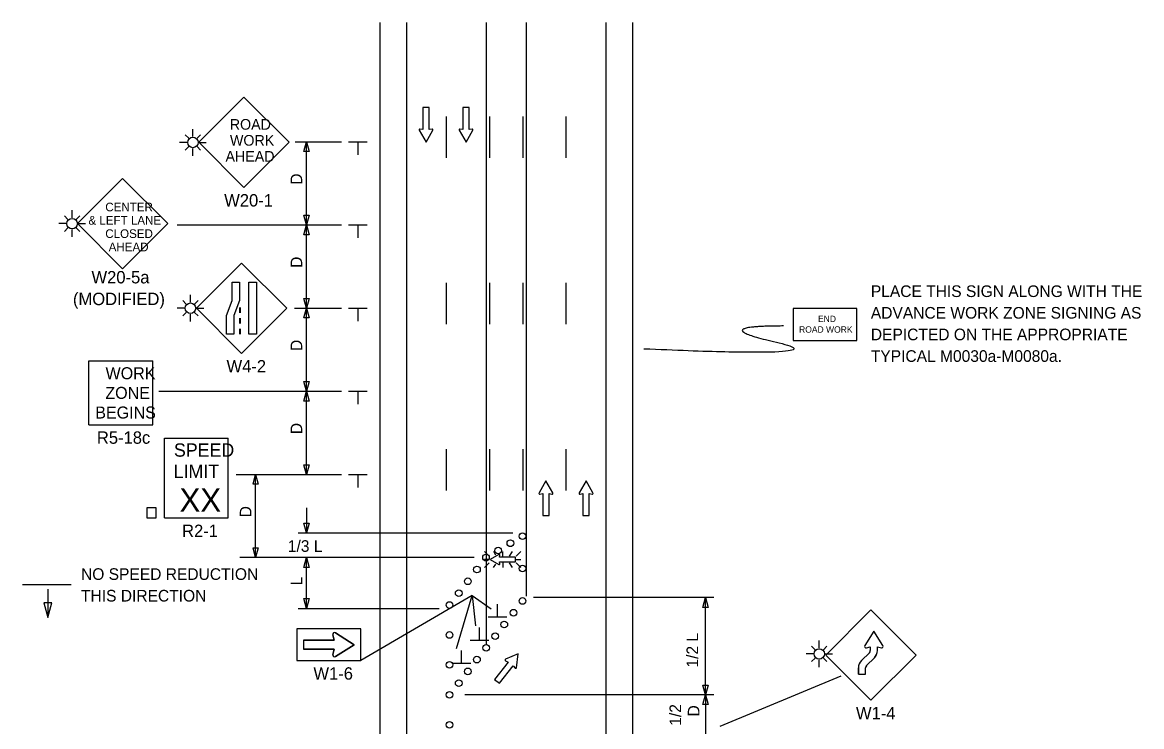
# Model space of a CAD drawing. Extents: x 16730 to 19504, y 5697 to 6911.
# Drawn here: x 16732 to 17406, y 6488 to 6911 of the extents above; entities that cross this region are included whole.
import ezdxf

# ---------------------------------------------------------------- set-up
doc = ezdxf.new("R2010")
doc.units = 0
for name, color, linetype in [('ALI_LEGAL_EX', 7, 'Continuous'), ('MT_SCRATCH_LEVEL_E', 7, 'Continuous'), ('PAVT_EDGE_EX', 7, 'Continuous'), ('TRAFFIC_SIGNS_PR', 7, 'Continuous'), ('TYPICAL_TEXT_DIMEN_PR', 7, 'Continuous')]:
    doc.layers.add(name, color=color, linetype=linetype)

msp = doc.modelspace()

# ---------------------------------------------------------------- linework, layer by layer
at = {"layer": 'ALI_LEGAL_EX'}
for points in [[(16987.43, 6854.77), (16987.43, 6829.77)], [(17013.43, 6854.77), (17013.43, 6829.77)], [(17033.43, 6854.77), (17033.43, 6829.77)], [(17059.43, 6854.77), (17059.43, 6829.77)], [(16987.43, 6754.77), (16987.43, 6729.77)], [(17013.43, 6754.77), (17013.43, 6729.77)], [(17033.43, 6754.77), (17033.43, 6729.77)], [(17059.43, 6754.77), (17059.43, 6729.77)], [(16987.43, 6654.77), (16987.43, 6629.77)], [(17013.43, 6654.77), (17013.43, 6629.77)], [(17033.43, 6654.77), (17033.43, 6629.77)], [(17059.43, 6654.77), (17059.43, 6629.77)]]:
    msp.add_lwpolyline(points, dxfattribs=at)
at = {"layer": 'MT_SCRATCH_LEVEL_E'}
for p, q in [((16977.1, 6860.07), (16973.36, 6860.07)), ((16973.36, 6860.07), (16973.36, 6846.81)), ((16977.1, 6860.07), (16973.36, 6860.07)), ((16973.36, 6860.07), (16973.36, 6846.81)), ((16977.1, 6846.81), (16977.1, 6860.07)), ((16977.1, 6846.81), (16977.1, 6860.07)), ((17001.17, 6860.07), (16997.43, 6860.07)), ((16997.43, 6860.07), (16997.43, 6846.81)), ((17001.17, 6860.07), (16997.43, 6860.07)), ((16997.43, 6860.07), (16997.43, 6846.81)), ((17001.17, 6846.81), (17001.17, 6860.07)), ((17001.17, 6846.81), (17001.17, 6860.07)), ((16971.1, 6846.44), (16975.25, 6839.2)), ((16971.1, 6846.44), (16975.25, 6839.2)), ((16973.36, 6846.81), (16971.58, 6847.12)), ((16973.36, 6846.81), (16971.58, 6847.12)), ((16975.25, 6839.2), (16979.36, 6846.44)), ((16975.25, 6839.2), (16979.36, 6846.44)), ((16978.88, 6847.12), (16977.1, 6846.81)), ((16978.88, 6847.12), (16977.1, 6846.81)), ((16995.18, 6846.44), (16999.32, 6839.2)), ((16995.18, 6846.44), (16999.32, 6839.2)), ((16997.43, 6846.81), (16995.65, 6847.12)), ((16997.43, 6846.81), (16995.65, 6847.12)), ((16999.32, 6839.2), (17003.43, 6846.44)), ((16999.32, 6839.2), (17003.43, 6846.44)), ((17002.95, 6847.12), (17001.17, 6846.81)), ((17002.95, 6847.12), (17001.17, 6846.81)), ((17047.37, 6635.6), (17043.26, 6628.36)), ((17047.37, 6635.6), (17043.26, 6628.36)), ((17051.52, 6628.36), (17047.37, 6635.6)), ((17051.52, 6628.36), (17047.37, 6635.6)), ((17071.54, 6635.6), (17067.43, 6628.36)), ((17071.54, 6635.6), (17067.43, 6628.36)), ((17075.69, 6628.36), (17071.54, 6635.6)), ((17075.69, 6628.36), (17071.54, 6635.6)), ((17043.74, 6627.67), (17045.52, 6627.99)), ((17043.74, 6627.67), (17045.52, 6627.99)), ((17045.52, 6627.99), (17045.52, 6614.73)), ((17045.52, 6627.99), (17045.52, 6614.73)), ((17049.26, 6614.73), (17049.26, 6627.99)), ((17049.26, 6627.99), (17051.04, 6627.67)), ((17049.26, 6614.73), (17049.26, 6627.99)), ((17049.26, 6627.99), (17051.04, 6627.67)), ((17067.91, 6627.67), (17069.69, 6627.99)), ((17067.91, 6627.67), (17069.69, 6627.99)), ((17069.69, 6627.99), (17069.69, 6614.73)), ((17069.69, 6627.99), (17069.69, 6614.73)), ((17073.43, 6614.73), (17073.43, 6627.99)), ((17073.43, 6627.99), (17075.21, 6627.67)), ((17073.43, 6614.73), (17073.43, 6627.99)), ((17073.43, 6627.99), (17075.21, 6627.67)), ((17045.52, 6614.73), (17049.26, 6614.73)), ((17045.52, 6614.73), (17049.26, 6614.73)), ((17069.69, 6614.73), (17073.43, 6614.73)), ((17069.69, 6614.73), (17073.43, 6614.73)), ((17024.64, 6526.66), (17016.51, 6516.2)), ((17024.64, 6526.66), (17016.51, 6516.2)), ((17023.05, 6527.5), (17024.64, 6526.66)), ((17023.05, 6527.5), (17024.64, 6526.66)), ((17030.78, 6531.53), (17023.09, 6528.34)), ((17030.78, 6531.53), (17023.09, 6528.34)), ((17029.61, 6523.27), (17030.78, 6531.53)), ((17029.61, 6523.27), (17030.78, 6531.53)), ((17019.46, 6513.9), (17027.6, 6524.36)), ((17019.46, 6513.9), (17027.6, 6524.36)), ((17027.6, 6524.36), (17028.81, 6523.03)), ((17027.6, 6524.36), (17028.81, 6523.03)), ((17016.51, 6516.2), (17019.46, 6513.9)), ((17016.51, 6516.2), (17019.46, 6513.9))]:
    msp.add_line(p, q, dxfattribs=at)
for centre, start, end in [((16971.51, 6846.66), 80.03619, 209.77312), ((16971.51, 6846.66), 80.03619, 209.77312), ((16978.96, 6846.67), 330.42484, 99.96381), ((16978.96, 6846.67), 330.42484, 99.96381), ((16995.59, 6846.66), 80.03619, 209.77312), ((16995.59, 6846.66), 80.03619, 209.77312), ((17003.03, 6846.67), 330.42484, 99.96381), ((17003.03, 6846.67), 330.42484, 99.96381), ((17043.67, 6628.13), 150.42484, 279.96381), ((17043.67, 6628.13), 150.42484, 279.96381), ((17051.11, 6628.13), 260.03619, 29.77312), ((17051.11, 6628.13), 260.03619, 29.77312), ((17067.84, 6628.13), 150.42484, 279.96381), ((17067.84, 6628.13), 150.42484, 279.96381), ((17075.28, 6628.13), 260.03619, 29.77312), ((17075.28, 6628.13), 260.03619, 29.77312), ((17023.27, 6527.91), 112.55885, 242.09782), ((17023.27, 6527.91), 112.55885, 242.09782), ((17029.15, 6523.35), 222.17021, 351.90713), ((17029.15, 6523.35), 222.17021, 351.90713)]:
    msp.add_arc(centre, 0.463, start, end, dxfattribs=at)
at = {"layer": 'PAVT_EDGE_EX'}
for p, q in [((16947.43, 6911.29), (16947.43, 6081.05)), ((16963.43, 6911.29), (16963.43, 6081.05)), ((17011.43, 6911.29), (17011.43, 6536.81)), ((17035.43, 6911.29), (17035.43, 6566.36)), ((17083.43, 6911.29), (17083.43, 6081.05)), ((17099.43, 6911.29), (17099.43, 6081.05))]:
    msp.add_line(p, q, dxfattribs=at)
at = {"layer": 'TRAFFIC_SIGNS_PR'}
for p, q in [((16865.66, 6866.41), (16838.48, 6839.22)), ((16892.85, 6839.22), (16865.66, 6866.41)), ((16832.5, 6841.63), (16830.4, 6843.73)), ((16835.02, 6842.67), (16835.02, 6847.17)), ((16837.53, 6841.63), (16839.64, 6843.73)), ((16831.86, 6839.11), (16827.02, 6839.11)), ((16832.5, 6836.6), (16830.4, 6834.49)), ((16835.02, 6831.15), (16835.02, 6835.56)), ((16837.53, 6836.6), (16839.64, 6834.49)), ((16838.17, 6839.11), (16843.05, 6839.11)), ((16838.48, 6839.22), (16865.66, 6812.04)), ((16865.66, 6812.04), (16892.85, 6839.22)), ((16792.68, 6817.45), (16765.49, 6790.27)), ((16819.87, 6790.27), (16792.68, 6817.45)), ((16759.83, 6792.78), (16757.72, 6794.89)), ((16762.34, 6793.82), (16762.34, 6798.32)), ((16764.85, 6792.78), (16766.96, 6794.89)), ((16759.18, 6790.27), (16754.35, 6790.27)), ((16759.82, 6787.76), (16757.72, 6785.65)), ((16764.85, 6787.76), (16766.96, 6785.65)), ((16765.49, 6790.27), (16770.37, 6790.27)), ((16765.49, 6790.27), (16792.68, 6763.08)), ((16792.68, 6763.08), (16819.87, 6790.27)), ((16762.34, 6782.3), (16762.34, 6786.71)), ((16864.28, 6766.57), (16837.13, 6739.42)), ((16891.44, 6739.42), (16864.28, 6766.57)), ((16833.52, 6742.97), (16833.52, 6747.47)), ((16831, 6741.93), (16828.9, 6744.04)), ((16836.03, 6741.93), (16838.14, 6744.04)), ((16830.36, 6739.42), (16825.52, 6739.42)), ((16831, 6736.9), (16828.9, 6734.79)), ((16833.52, 6731.45), (16833.52, 6735.86)), ((16836.03, 6736.9), (16838.14, 6734.8)), ((16836.67, 6739.42), (16841.55, 6739.42)), ((16837.13, 6739.42), (16864.28, 6712.26)), ((16863.04, 6739.91), (16863.04, 6736.71)), ((16863.44, 6739.91), (16863.44, 6736.71)), ((16864.28, 6712.26), (16891.44, 6739.42)), ((16863.04, 6733.51), (16863.04, 6730.31)), ((16863.04, 6727.11), (16863.04, 6723.91)), ((16863.44, 6733.51), (16863.44, 6730.31)), ((16863.44, 6727.11), (16863.44, 6723.91)), ((16772.45, 6669.36), (16772.45, 6707.76)), ((16772.45, 6707.76), (16810.85, 6707.76)), ((16810.85, 6669.36), (16810.85, 6707.76)), ((16772.45, 6669.36), (16810.85, 6669.36)), ((16817.83, 6661.29), (16856.23, 6661.29)), ((16817.83, 6613.29), (16817.83, 6661.29)), ((16856.23, 6613.29), (16856.23, 6661.29)), ((16817.83, 6613.29), (16856.23, 6613.29)), ((17010.52, 6593.2), (17013.34, 6590.39)), ((17017.24, 6591.02), (17015.98, 6593.2)), ((17021.42, 6590.39), (17021.42, 6593.2)), ((17025.56, 6590.39), (17027.19, 6593.2)), ((17029.51, 6590.39), (17032.33, 6593.21)), ((17013.34, 6588.35), (17010.52, 6588.35)), ((17010.52, 6583.5), (17013.34, 6586.32)), ((17021.42, 6586.32), (17021.42, 6583.5)), ((17027.21, 6583.5), (17025.58, 6586.32)), ((17029.51, 6588.35), (17032.33, 6588.35)), ((17029.51, 6586.32), (17032.33, 6583.5)), ((17015.95, 6583.5), (17017.16, 6585.59)), ((17242.92, 6557.97), (17215.77, 6530.82)), ((17270.07, 6530.82), (17242.92, 6557.97)), ((16901.58, 6539.92), (16919.98, 6539.92)), ((16901.58, 6539.92), (16901.58, 6534.32)), ((16919.98, 6539.92), (16919.14, 6542.98)), ((16920.82, 6544.22), (16931.98, 6537.12)), ((17211.86, 6535.09), (17211.86, 6539.59)), ((16919.98, 6534.32), (16901.58, 6534.32)), ((16919.14, 6531.26), (16919.98, 6534.32)), ((16931.98, 6537.12), (16920.82, 6530.02)), ((17209.34, 6534.05), (17207.24, 6536.16)), ((17214.37, 6534.05), (17216.48, 6536.16)), ((17237.26, 6527.57), (17241.98, 6532.28)), ((17241.98, 6532.28), (17237.26, 6527.57)), ((17208.7, 6531.54), (17203.87, 6531.54)), ((17209.34, 6529.03), (17207.24, 6526.92)), ((17211.86, 6523.57), (17211.86, 6527.98)), ((17214.37, 6529.03), (17216.48, 6526.92)), ((17215.01, 6531.54), (17219.89, 6531.54)), ((17215.77, 6530.82), (17242.92, 6503.67)), ((17240.32, 6524.52), (17245.03, 6529.23)), ((17240.32, 6524.52), (17245.03, 6529.23)), ((17242.92, 6503.67), (17270.07, 6530.82)), ((17235.4, 6519.45), (17235.4, 6523.15)), ((17235.4, 6519.45), (17239.71, 6519.45)), ((17239.71, 6519.45), (17239.71, 6523.15))]:
    msp.add_line(p, q, dxfattribs=at)
for points in [[(16863.04, 6755.15), (16863.04, 6743.97), (16859.69, 6735.09), (16859.69, 6723.91), (16855.2, 6723.91), (16855.2, 6735.09), (16858.54, 6743.97), (16858.54, 6755.15)], [(16873.17, 6755.15), (16873.17, 6723.91), (16868.68, 6723.91), (16868.68, 6755.15)], [(17196.1, 6719.96), (17234.5, 6719.96), (17234.5, 6739.16), (17196.1, 6739.16)], [(16807.23, 6613.29), (16812.82, 6613.29), (16812.82, 6619.46), (16807.23, 6619.46)], [(16897.58, 6527.52), (16935.98, 6527.52), (16935.98, 6546.72), (16897.58, 6546.72)]]:
    msp.add_lwpolyline(points, close=True, dxfattribs=at)
for points in [[(17019.1, 6591.37), (17013.79, 6588.35), (17019.1, 6585.31)], [(17019.6, 6585.67), (17019.37, 6586.97), (17029.09, 6586.97), (17029.09, 6589.71), (17019.37, 6589.71), (17019.6, 6591.01)], [(16919.14, 6542.98), (16919.98, 6539.92), (16901.58, 6539.92), (16901.58, 6534.32), (16919.98, 6534.32), (16919.14, 6531.26)], [(16920.82, 6530.02), (16931.98, 6537.12), (16920.82, 6544.22)], [(17250.19, 6536.56), (17244.7, 6545.17), (17239.22, 6536.56)], [(17250.18, 6536.56), (17244.7, 6545.17), (17239.22, 6536.56)], [(17240.18, 6535.26), (17242.54, 6535.91), (17242.54, 6533.61)], [(17240.18, 6535.26), (17241.02, 6535.49), (17242.54, 6535.91), (17242.54, 6533.61)], [(17246.85, 6533.54), (17246.86, 6535.91), (17249.22, 6535.26)], [(17235.4, 6523.15), (17235.4, 6519.45), (17239.71, 6519.45), (17239.71, 6523.15)]]:
    msp.add_lwpolyline(points, dxfattribs=at)
for centre, radius in [((16835.02, 6839.11), 3.15), ((16762.34, 6790.27), 3.15), ((16833.52, 6739.42), 3.15), ((17025.99, 6598.09), 2), ((17033.32, 6602.39), 2), ((17018.66, 6593.78), 2), ((17011.34, 6589.47), 2), ((17005.92, 6582.34), 2), ((17033.32, 6582.9), 2), ((17000.42, 6575.21), 2), ((16994.93, 6568.08), 2), ((16989.44, 6560.95), 2), ((16989.44, 6560.95), 2), ((17033.32, 6563.4), 2), ((17027.84, 6556.34), 2), ((17022.35, 6549.29), 2), ((16989.44, 6542.95), 2), ((17016.87, 6542.23), 2), ((17011.38, 6535.18), 2), ((17211.86, 6531.54), 3.15), ((16989.44, 6524.95), 2), ((17005.89, 6528.12), 2), ((17000.41, 6521.06), 2), ((16994.92, 6514.01), 2), ((16989.43, 6506.95), 2), ((16989.44, 6488.95), 2)]:
    msp.add_circle(centre, radius, dxfattribs=at)
for centre, radius, start, end in [((17019.26, 6591.07), 0.341, 350.73078, 118.89165), ((17019.26, 6585.61), 0.341, 241.48329, 9.95933), ((16920.22, 6543.28), 1.12, 57.53038, 195.32692), ((16920.22, 6543.28), 1.12, 57.53038, 195.32692), ((17239.95, 6536.09), 0.864, 147.52044, 285.3986), ((17239.95, 6536.09), 0.866, 147.52881, 285.38519), ((17240.69, 6533.61), 1.85, 314.21254, 0), ((17240.69, 6533.61), 1.85, 314.2123, 0.1238), ((17240.69, 6533.61), 6.17, 314.21254, 359.38189), ((17240.69, 6533.61), 6.17, 314.76872, 359.37555), ((17249.45, 6536.1), 0.866, 254.67989, 32.28036), ((16920.22, 6530.96), 1.12, 164.67308, 302.46962), ((16920.22, 6530.96), 1.12, 164.67308, 302.46963), ((17241.56, 6523.15), 6.17, 134.21254, 180), ((17241.56, 6523.15), 6.17, 134.21254, 180), ((17241.57, 6523.15), 6.17, 134.21172, 180), ((17241.56, 6523.15), 1.85, 134.21254, 180), ((17241.57, 6523.15), 1.85, 132.37199, 180)]:
    msp.add_arc(centre, radius, start, end, dxfattribs=at)
msp.add_open_spline([(17190.41, 6728.74), (17143.17, 6728.74), (17228.2, 6709.4), (17106.38, 6714.89)], degree=2, dxfattribs=at)
at = {"layer": 'TYPICAL_TEXT_DIMEN_PR'}
for p, q in [((16896.48, 6839.48), (16924.34, 6839.48)), ((16898.34, 6839.48), (16924.34, 6839.48)), ((16901.77, 6833.61), (16903.34, 6839.48)), ((16903.34, 6789.48), (16903.34, 6839.48)), ((16903.34, 6839.48), (16904.91, 6833.61)), ((16928.59, 6839.48), (16939.84, 6839.48)), ((16934.21, 6839.48), (16934.21, 6831.69)), ((16903.34, 6833.61), (16901.77, 6833.61)), ((16904.91, 6833.61), (16903.34, 6833.61)), ((16903.34, 6789.48), (16901.77, 6795.34)), ((16901.77, 6795.34), (16903.34, 6795.34)), ((16903.34, 6795.34), (16904.91, 6795.34)), ((16904.91, 6795.34), (16903.34, 6789.48)), ((16825.58, 6789.48), (16924.34, 6789.48)), ((16898.34, 6789.48), (16924.34, 6789.48)), ((16901.77, 6783.61), (16903.34, 6789.48)), ((16903.34, 6789.48), (16904.91, 6783.61)), ((16903.34, 6739.48), (16903.34, 6789.48)), ((16928.59, 6789.48), (16939.84, 6789.48)), ((16934.21, 6789.48), (16934.21, 6781.69)), ((16903.34, 6783.61), (16901.77, 6783.61)), ((16904.91, 6783.61), (16903.34, 6783.61)), ((16903.34, 6739.48), (16901.77, 6745.34)), ((16901.77, 6745.34), (16903.34, 6745.34)), ((16903.34, 6745.34), (16904.91, 6745.34)), ((16904.91, 6745.34), (16903.34, 6739.48)), ((16896.04, 6739.48), (16924.34, 6739.48)), ((16901.77, 6733.61), (16903.34, 6739.48)), ((16903.34, 6739.48), (16904.91, 6733.61)), ((16903.34, 6689.48), (16903.34, 6739.48)), ((16928.59, 6739.48), (16939.84, 6739.48)), ((16934.21, 6739.48), (16934.21, 6731.69)), ((16903.34, 6733.61), (16901.77, 6733.61)), ((16904.91, 6733.61), (16903.34, 6733.61)), ((16903.34, 6689.48), (16901.77, 6695.34)), ((16901.77, 6695.34), (16903.34, 6695.34)), ((16903.34, 6695.34), (16904.91, 6695.34)), ((16904.91, 6695.34), (16903.34, 6689.48)), ((16814.42, 6689.48), (16924.34, 6689.48)), ((16901.77, 6683.61), (16903.34, 6689.48)), ((16903.34, 6639.48), (16903.34, 6689.48)), ((16903.34, 6689.48), (16904.91, 6683.61)), ((16928.59, 6689.48), (16939.84, 6689.48)), ((16934.21, 6689.48), (16934.21, 6681.69)), ((16903.34, 6683.61), (16901.77, 6683.61)), ((16904.91, 6683.61), (16903.34, 6683.61)), ((16903.34, 6639.48), (16901.77, 6645.34)), ((16901.77, 6645.34), (16903.34, 6645.34)), ((16903.34, 6645.34), (16904.91, 6645.34)), ((16904.91, 6645.34), (16903.34, 6639.48)), ((16861.13, 6639.48), (16924.34, 6639.48)), ((16871.19, 6633.61), (16872.76, 6639.48)), ((16872.76, 6633.61), (16871.19, 6633.61)), ((16872.76, 6639.48), (16874.33, 6633.61)), ((16872.76, 6589.48), (16872.76, 6639.48)), ((16874.33, 6633.61), (16872.76, 6633.61)), ((16928.59, 6639.48), (16939.84, 6639.48)), ((16934.21, 6639.48), (16934.21, 6631.69)), ((16903.34, 6619.32), (16903.34, 6604.4)), ((16903.34, 6604.4), (16901.77, 6610.26)), ((16901.77, 6610.26), (16903.34, 6610.26)), ((16903.34, 6610.26), (16904.91, 6610.26)), ((16904.91, 6610.26), (16903.34, 6604.4)), ((16898.34, 6604.4), (17027.47, 6604.4)), ((16872.76, 6589.48), (16871.19, 6595.34)), ((16871.19, 6595.34), (16872.76, 6595.34)), ((16872.76, 6595.34), (16874.33, 6595.34)), ((16874.33, 6595.34), (16872.76, 6589.48)), ((17004.25, 6589.48), (16863.24, 6589.48)), ((17004.25, 6589.48), (16872.76, 6589.48)), ((16901.77, 6583.61), (16903.34, 6589.48)), ((16903.34, 6558.94), (16903.34, 6589.48)), ((16903.34, 6589.48), (16904.91, 6583.61)), ((16903.34, 6583.61), (16901.77, 6583.61)), ((16904.91, 6583.61), (16903.34, 6583.61)), ((16761.85, 6573.04), (16732.41, 6573.04)), ((16747.67, 6570.54), (16747.67, 6553.42)), ((17003.11, 6566.74), (16935.98, 6527.52)), ((16993.63, 6534.8), (17003.11, 6566.74)), ((17003.11, 6566.74), (17005.01, 6548.49)), ((17003.11, 6566.74), (17014.49, 6558.76)), ((16747.67, 6562.21), (16745.32, 6562.21)), ((16745.32, 6562.21), (16747.67, 6553.42)), ((16747.67, 6553.42), (16750.03, 6562.21)), ((16750.03, 6562.21), (16747.67, 6562.21)), ((16898.34, 6558.94), (16983.16, 6558.94)), ((16903.34, 6558.94), (16901.77, 6564.8)), ((16901.77, 6564.8), (16903.34, 6564.8)), ((16903.34, 6564.8), (16904.91, 6564.8)), ((16904.91, 6564.8), (16903.34, 6558.94)), ((17018.34, 6553.59), (17018.34, 6561.38)), ((17148.43, 6565.4), (17039.85, 6565.4)), ((17141.86, 6559.54), (17143.43, 6565.4)), ((17143.43, 6559.54), (17141.86, 6559.54)), ((17143.43, 6506.95), (17143.43, 6565.4)), ((17143.43, 6565.4), (17145, 6559.54)), ((17145, 6559.54), (17143.43, 6559.54)), ((17023.97, 6553.59), (17012.72, 6553.59)), ((17007.51, 6539.66), (17007.51, 6547.45)), ((17013.14, 6539.66), (17001.89, 6539.66)), ((16996.69, 6525.74), (16996.69, 6533.52)), ((17002.31, 6525.74), (16991.06, 6525.74)), ((17143.43, 6506.95), (17141.86, 6512.81)), ((17141.86, 6512.81), (17143.43, 6512.81)), ((17143.43, 6512.81), (17145, 6512.81)), ((17145, 6512.81), (17143.43, 6506.95)), ((17224.76, 6518.18), (17151.94, 6487.89)), ((17148.43, 6506.95), (16998.6, 6506.95)), ((17141.86, 6501.09), (17143.43, 6506.95)), ((17143.43, 6506.95), (17145, 6501.09)), ((17143.43, 6506.95), (17143.43, 6481.95)), ((17143.43, 6501.09), (17141.86, 6501.09)), ((17145, 6501.09), (17143.43, 6501.09))]:
    msp.add_line(p, q, dxfattribs=at)

# ---------------------------------------------------------------- texts
at = {"layer": 'TRAFFIC_SIGNS_PR'}
for s, height, p in [('ROAD', 6.408, (16857.19, 6846.77)), ('WORK', 6.408, (16857.3, 6837.16)), ('AHEAD', 6.408, (16854.61, 6827.54)), ('W20-1', 7.449, (16853.82, 6800.58)), ('CENTER', 5.206, (16782.3, 6797.68)), ('& LEFT LANE', 5.2065, (16772.16, 6789.67)), ('CLOSED', 5.206, (16782.3, 6781.66)), ('AHEAD', 5.206, (16784.33, 6773.65)), ('W20-5a', 7.449, (16773.99, 6754.35)), ('(MODIFIED)', 7.449, (16762.83, 6741.3)), ('PLACE THIS SIGN ALONG WITH THE', 7, (17242.88, 6746.16)), ('END', 3.831, (17211.1, 6731.09)), ('ADVANCE WORK ZONE SIGNING AS', 7, (17242.88, 6733.16)), ('ROAD WORK', 3.831, (17199.71, 6724.71)), ('DEPICTED ON THE APPROPRIATE', 7, (17242.88, 6720.16)), ('TYPICAL M0030a-M0080a.', 7, (17242.88, 6707.16)), ('W4-2', 7.44, (16855.24, 6700.82)), ('WORK', 7.217, (16782.45, 6696.72)), ('ZONE', 7.217, (16782.33, 6684.91)), ('BEGINS', 7.217, (16776.25, 6673.1)), ('R5-18c', 7.44, (16777.26, 6657.92)), ('SPEED', 8, (16823.6, 6650.15)), ('LIMIT', 8, (16823.44, 6637.35)), ('XX', 14.031, (16826.95, 6617.05)), ('R2-1', 7.44, (16828.51, 6601.85)), ('W1-6', 7.44, (16907.52, 6516.08)), ('W1-4', 7.44, (17233.93, 6492.23))]:
    msp.add_text(s, height=height, dxfattribs=at).set_placement(p)
at = {"layer": 'TYPICAL_TEXT_DIMEN_PR'}
for s, p in [('D', (16900.78, 6813.69)), ('D', (16900.78, 6763.69)), ('D', (16900.78, 6713.69)), ('D', (16900.78, 6663.69)), ('D', (16870.2, 6613.69)), ('L', (16900.78, 6572.81)), ('1/2 L', (17138.98, 6523.36)), ('1/2', (17128.75, 6488.37)), ('D', (17139.75, 6493.94))]:
    msp.add_text(s, height=7, rotation=90, dxfattribs=at).set_placement(p)
for s, p in [('1/3 L', (16892.12, 6592.93)), ('NO SPEED REDUCTION', (16767.69, 6576.06)), ('THIS DIRECTION', (16767.69, 6563.06))]:
    msp.add_text(s, height=7, dxfattribs=at).set_placement(p)

doc.saveas('drawing.dxf')
